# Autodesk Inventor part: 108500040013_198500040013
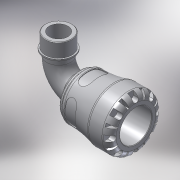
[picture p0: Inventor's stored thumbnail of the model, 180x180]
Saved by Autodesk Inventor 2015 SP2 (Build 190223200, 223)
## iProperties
Created: 2016-12
Part Number: 108500040013_198500040013
Material: PVC-Piping
Description: PLASSON 90° ELBOW WITH THREADED MALE OFFTAKE 40X1.1/4" SERIES 1
Document SubType Name: Modeling
Designer: KIM
Mass: 279.102 g
Surface Area: 485.736 cm^2
Volume: 199.358 cm^3
Density: 1.4 g/cm^3
Appearance: Smooth - White
Author: KIM
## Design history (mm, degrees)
derived "1085.ipt"
feature "Solid1::1085.ipt"
tag "TaggingFeature1"
body "Solid1"
other parameters: "d1" = 29.82, "d8" = 59.5, "d13" = 8, "d14" = 8, "d15" = 0, "d17" = 360 deg, "d19" = 8 deg, "d20" = 0.8, "d21" = 0.8, "d22" = 8 deg, "d24" = 0, "d26" = 360 deg, "d33" = 7, "d43" = 54.6, "d51" = 0.7, "d54" = 14, "d55" = 8.8, "d57" = 15.68, "d58" = 0, "d74" = 0, "d78" = 71, "d82" = 0.8, "d115" = 360 deg, "d207" = 90 deg, "d228" = 11.9, "d247" = 1.4, "d248" = 4.26, "d268" = 32.725, "d269" = 4.26, "d270" = 107, "d276" = 41.91, "d277" = 21, "d278" = 46.101, "d279" = 58, "d280" = 23.1, "d281" = 6.2865, "d283" = 37.719, "d286" = 0, "d287" = 0, "d288" = 29.337, "d290" = 8.4405, "d292" = 30 deg, "l_" = 71, "A_" = 107, "A_1" = 58, "l_2" = 21, "R_" = 41.91, "d9" = 10, "d289" = 29.337
